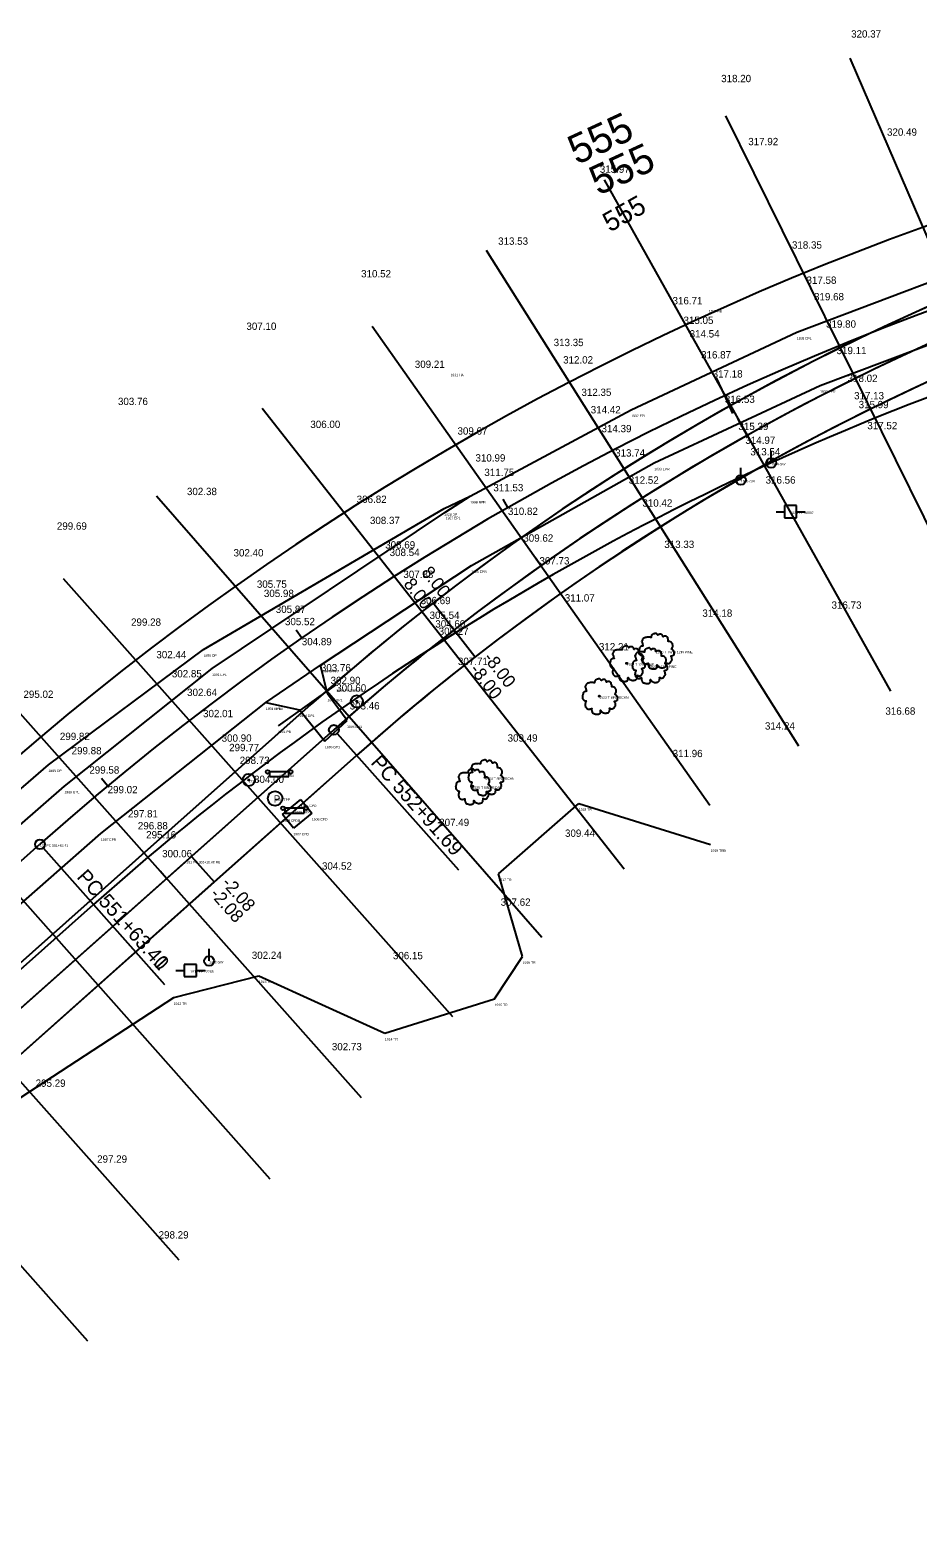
# Model space of a CAD drawing. Extents: x 49683 to 58852, y 49525 to 54803.
# Drawn here: x 56026 to 56390, y 53498 to 54115 of the extents above; entities that cross this region are included whole.
import ezdxf

# ---------------------------------------------------------------- set-up
doc = ezdxf.new("R2010")
doc.units = 0
for name, color, linetype in [('Level 1', 7, 'Continuous'), ('Level 11', 7, 'Continuous'), ('Level 12', 7, 'Continuous'), ('Level 13', 7, 'Continuous'), ('Level 19', 7, 'Continuous'), ('Level 20', 7, 'Continuous'), ('Level 21', 7, 'Continuous'), ('Level 29', 7, 'Continuous'), ('Level 3', 7, 'Continuous'), ('Level 32', 7, 'Continuous'), ('Level 50', 7, 'Continuous'), ('Level 51', 7, 'Continuous'), ('Level 53', 7, 'Continuous'), ('Level 56', 7, 'Continuous'), ('Level 58', 7, 'Continuous'), ('Level 59', 7, 'Continuous'), ('Level 6', 7, 'Continuous'), ('Level 61', 7, 'Continuous'), ('Level 62', 7, 'Continuous'), ('Level 63', 7, 'Continuous'), ('Level 8', 7, 'Continuous'), ('Level 9', 7, 'Continuous')]:
    doc.layers.add(name, color=color, linetype=linetype)

# ---------------------------------------------------------------- blocks, each defined once
blk = doc.blocks.new('IP')
at = {"layer": 'Level 12'}
for radius in [2.5, 0.25]:
    blk.add_circle((0, 0), radius, dxfattribs=at)
blk = doc.blocks.new('TBX')
at = {"layer": 'Level 9'}
for p, q in [((3.99, 1.14), (-4.01, 1.14)), ((-4.01, 1.14), (-4.01, -0.82)), ((3.99, -0.82), (3.99, 1.14)), ((-4.01, -0.82), (3.99, -0.82))]:
    blk.add_line(p, q, dxfattribs=at)
for centre in [(-4.76, 1.14), (4.74, 1.14)]:
    blk.add_circle(centre, 0.75, dxfattribs=at)
blk = doc.blocks.new('TPP')
at = {"layer": 'Level 9'}
blk.add_circle((0, 0), 3, dxfattribs=at)
blk.add_text('P', height=3, dxfattribs=at).set_placement((-0.59, -1.73))
blk = doc.blocks.new('GW')
at = {"layer": 'Level 9'}
blk.add_line((0, 0), (0, 5), dxfattribs=at)
blk.add_circle((0, 0), 2, dxfattribs=at)
blk = doc.blocks.new('PP')
at = {"layer": 'Level 9'}
for p, q in [((2.53, 2.45), (-2.47, 2.45)), ((-2.47, 2.45), (-2.47, -2.55)), ((2.53, -2.55), (2.53, 2.45)), ((-5.91, -0.11), (-2.44, -0.11)), ((-2.47, -2.55), (2.53, -2.55)), ((2.45, -0.11), (6.09, -0.11))]:
    blk.add_line(p, q, dxfattribs=at)
blk = doc.blocks.new('T1')
at = {"layer": 'Level 11'}
for centre, radius in [((0, 0), 0.25), ((-0.01, -0.02), 0.0001)]:
    blk.add_circle(centre, radius, dxfattribs=at)
for points in [[(0.13, 7.17), (-0.17, 7.19), (-0.49, 7.09), (-0.74, 6.99), (-0.97, 6.92), (-1.19, 6.82), (-1.49, 6.64), (-1.72, 6.44), (-1.84, 6.19), (-1.89, 5.97), (-1.94, 5.69), (-1.94, 5.52), (-2.07, 5.49), (-2.22, 5.52), (-2.47, 5.59), (-2.72, 5.59), (-2.97, 5.59), (-3.32, 5.57), (-3.67, 5.57), (-3.94, 5.52), (-4.27, 5.47), (-4.64, 5.34), (-4.99, 5.22), (-5.29, 4.97), (-5.54, 4.49), (-5.67, 4.14), (-5.82, 3.89), (-5.67, 3.44), (-5.49, 3.09), (-5.47, 2.89), (-5.39, 2.47), (-5.29, 2.24), (-5.17, 2.04), (-5.24, 2.02), (-5.62, 1.97), (-5.92, 1.87), (-6.34, 1.64), (-6.57, 1.42), (-6.67, 1.09), (-6.69, 0.75), (-6.79, 0.55), (-6.87, 0.27), (-6.89, 0.2), (-6.94, -0.13), (-6.84, -0.58), (-6.82, -0.93), (-6.69, -1.15), (-6.54, -1.33), (-6.37, -1.58), (-5.97, -1.8), (-5.64, -1.9), (-5.44, -1.93), (-5.62, -2.43), (-5.67, -2.78), (-5.79, -3.18), (-5.79, -3.25), (-5.84, -3.73), (-5.69, -4.05), (-5.62, -4.43), (-5.44, -4.65), (-5.17, -4.95), (-4.84, -5.18), (-4.34, -5.3), (-3.94, -5.28), (-3.37, -5.1), (-3.12, -5.03), (-3.14, -5.2), (-3.12, -5.58), (-3.12, -6), (-2.97, -6.33), (-2.87, -6.6), (-2.72, -6.85), (-2.39, -7.08), (-1.99, -7.15), (-1.57, -7.3), (-1.12, -7.38), (-0.62, -7.4), (-0.02, -7.25), (0.26, -7.13), (0.36, -6.95), (0.56, -6.58), (0.51, -6.35), (0.53, -5.75), (0.63, -5.93), (0.81, -6.28), (1.31, -6.58), (1.71, -6.75), (2.18, -6.9), (2.48, -6.98), (2.96, -6.9), (3.33, -6.83), (3.71, -6.7), (4.01, -6.43), (4.18, -6.15), (4.23, -5.88), (4.31, -5.5), (4.36, -5.33)], [(4.36, -5.33), (4.28, -5.15), (4.23, -4.9), (4.31, -4.93), (4.48, -4.98), (4.75, -5.1), (4.98, -5.18), (5.3, -5.15), (5.58, -5.05), (6.03, -4.78), (6.3, -4.3), (6.58, -3.9), (6.65, -3.58), (6.6, -3.35), (6.58, -2.85), (6.38, -2.6), (6.33, -2.48), (6.23, -2.08), (6.3, -2.03), (6.58, -1.98), (6.95, -1.85), (7.23, -1.73), (7.45, -1.55), (7.53, -1.33), (7.5, -0.93), (7.55, -0.53), (7.48, -0.38), (7.38, -0.23), (7.3, -0.03), (7.15, 0.12), (7.05, 0.27), (6.95, 0.37), (6.83, 0.52), (6.65, 0.65), (6.5, 0.7), (6.45, 0.85), (6.6, 1.04), (6.65, 1.14), (6.68, 1.37), (6.9, 1.72), (6.95, 2.12), (6.9, 2.54), (6.85, 2.82), (6.7, 3.09), (6.5, 3.34), (6.38, 3.52), (6.2, 3.64), (5.88, 3.77), (5.63, 3.82), (5.28, 3.82), (5.08, 3.87), (5.1, 3.92), (5.1, 4.07), (5.1, 4.34), (5.03, 4.79), (4.88, 5.29), (4.88, 5.32), (4.78, 5.57), (4.56, 5.77), (4.38, 5.87), (4.18, 5.99), (3.93, 6.02), (3.63, 6.02), (3.36, 5.97), (3.16, 5.87), (2.98, 5.74), (2.91, 5.89), (2.81, 6.19), (2.76, 6.34), (2.61, 6.52), (2.38, 6.72), (1.93, 6.84), (1.31, 6.77), (1.01, 6.57), (0.86, 6.39), (0.81, 6.52), (0.61, 6.72), (0.51, 6.89), (0.33, 7.02), (0.18, 7.12), (0.08, 7.17)]]:
    blk.add_spline(points, degree=3, dxfattribs=at)

msp = doc.modelspace()

# ---------------------------------------------------------------- linework, layer by layer
at = {"layer": 'Level 1'}
for p, q in [((56311, 53965.34), (56307.64, 53972.6)), ((56314.36, 53958.08), (56311, 53965.34)), ((56222.17, 53919.48), (56220.18, 53922.95)), ((56137.67, 53866.06), (56135.39, 53869.34)), ((56058.16, 53805.47), (56055.59, 53808.55)), ((55534.58, 53340.86), (56030.42, 53781.6)), ((56031.75, 53780.11), (56080.5, 53725.26))]:
    msp.add_line(p, q, dxfattribs=at)
msp.add_circle((56030.42, 53781.6), 2, dxfattribs=at)
at = {"layer": 'Level 11'}
for p, q in [((56218.32, 53769.53), (56251.21, 53798.33)), ((56251.21, 53798.33), (56305.22, 53781.48)), ((56228.2, 53735.68), (56218.32, 53769.53)), ((56216.72, 53718.3), (56228.2, 53735.68)), ((56085.22, 53718.79), (56120.13, 53727.76)), ((56120.13, 53727.76), (56171.75, 53704.22)), ((55996.99, 53661.35), (56085.22, 53718.79)), ((56171.75, 53704.22), (56216.72, 53718.3))]:
    msp.add_line(p, q, dxfattribs=at)
at = {"layer": 'Level 13'}
msp.add_line((55556.51, 53316.2), (56052.34, 53756.94), dxfattribs=at)
for radius, start in [(1178.92, 86.60044), (1112.92, 108.44495)]:
    msp.add_arc((56791.72, 52925.13), radius, start, 131.63335, dxfattribs=at)
at = {"layer": 'Level 19'}
for p, q in [((56320.22, 53949.03), (56316.31, 53956.01)), ((56320.22, 53949.03), (56324.13, 53942.05)), ((56235.67, 53895.71), (56233.36, 53898.98)), ((56157.09, 53833.94), (56154.45, 53836.95)), ((54181.77, 52078.16), (56150.85, 53828.45)), ((56152.18, 53826.95), (56201.86, 53771.06)), ((56082.32, 53767.53), (56079.66, 53770.52))]:
    msp.add_line(p, q, dxfattribs=at)
msp.add_circle((56150.85, 53828.45), 2, dxfattribs=at)
msp.add_arc((56791.96, 53107.19), 965, 83.49443, 131.63337, dxfattribs=at)
at = {"layer": 'Level 20'}
for p, q in [((54172.47, 52088.62), (56141.55, 53838.91)), ((54191.07, 52067.7), (56160.15, 53817.98))]:
    msp.add_line(p, q, dxfattribs=at)
for radius, start in [(979, 83.49447), (951, 83.49446)]:
    msp.add_arc((56791.96, 53107.19), radius, start, 131.63337, dxfattribs=at)
at = {"layer": 'Level 29'}
for p, q in [((56311, 53965.34), (56307.65, 53972.6)), ((56222.17, 53919.48), (56220.18, 53922.95)), ((56137.67, 53866.06), (56135.39, 53869.34)), ((56058.16, 53805.47), (56055.6, 53808.55)), ((55534.58, 53340.86), (56030.42, 53781.6)), ((56031.75, 53780.11), (56081.44, 53724.2))]:
    msp.add_line(p, q, dxfattribs=at)
msp.add_circle((56030.42, 53781.6), 2, dxfattribs=at)
msp.add_arc((56791.72, 52925.13), 1145.92, 83.49443, 131.63333, dxfattribs=at)
at = {"layer": 'Level 3'}
for p, q in [((56340.54, 53991.29), (56414.45, 54019.29)), ((56350.09, 53969.49), (56420.81, 53996.17)), ((56272.68, 53959.54), (56340.54, 53991.29)), ((56282.12, 53937.76), (56350.09, 53969.49)), ((56206.74, 53924.16), (56272.68, 53959.54)), ((56207.19, 53895.72), (56282.12, 53937.76)), ((56196.7, 53917.72), (56206.74, 53924.16)), ((56100.96, 53853.53), (56196.7, 53917.72)), ((56145.4, 53854.95), (56207.19, 53895.72)), ((56040.5, 53805.43), (56100.96, 53853.53)), ((56122.95, 53839.6), (56145.4, 53854.95)), ((56055.41, 53785.96), (56122.95, 53839.6)), ((55974.42, 53747.84), (56040.5, 53805.43)), ((55989.61, 53728.42), (56055.41, 53785.96))]:
    msp.add_line(p, q, dxfattribs=at)
at = {"layer": 'Level 50'}
for p, q in [((56362.31, 54103.5), (56457.35, 53883.12)), ((56311.29, 54079.91), (56417.61, 53864.75)), ((56261.55, 54053.71), (56378.88, 53844.34)), ((56213.25, 54024.97), (56341.26, 53821.96)), ((56166.49, 53993.77), (56304.84, 53797.66)), ((56121.41, 53960.18), (56269.74, 53771.5)), ((56078.14, 53924.31), (56236.03, 53743.57)), ((56039.97, 53890.44), (56199.41, 53711.06)), ((56002.6, 53857.22), (56162.04, 53677.84)), ((55965.23, 53824), (56124.67, 53644.62)), ((55927.86, 53790.78), (56087.3, 53611.4)), ((55890.49, 53757.56), (56049.93, 53578.19))]:
    msp.add_line(p, q, dxfattribs=at)
at = {"layer": 'Level 6'}
msp.add_line((56151.85, 53847.05), (56127.97, 53830.15), dxfattribs=at)
at = {"layer": 'Level 63'}
for p, q in [((56200.06, 53869.35), (56191.47, 53880.4)), ((56200.06, 53869.35), (56191.47, 53880.4)), ((56208.65, 53858.29), (56200.06, 53869.35)), ((56208.65, 53858.29), (56200.06, 53869.35)), ((56141.55, 53838.91), (56008.51, 53720.65)), ((56017.81, 53710.19), (56150.85, 53828.45)), ((56150.85, 53828.45), (56092.55, 53776.62)), ((56101.85, 53766.16), (56160.15, 53817.98)), ((54181.77, 52078.16), (56092.55, 53776.62)), ((56092.55, 53776.62), (56101.85, 53766.16)), ((56092.55, 53776.62), (56101.85, 53766.16)), ((56101.85, 53766.16), (54191.07, 52067.7))]:
    msp.add_line(p, q, dxfattribs=at)
for radius, start, end in [(979, 87.29416, 127.83345), (965, 87.29416, 127.83345), (965, 87.29416, 127.83345), (951, 87.29416, 127.83345), (979, 127.83345, 131.63336), (965, 127.83345, 131.63336), (965, 127.83345, 131.63336), (951, 127.83345, 131.63336)]:
    msp.add_arc((56791.96, 53107.19), radius, start, end, dxfattribs=at)
at = {"layer": 'Level 8'}
for p, q in [((56196.03, 53919.16), (56206.74, 53924.16)), ((56097.49, 53861.41), (56196.03, 53919.16)), ((56033.94, 53814.18), (56097.49, 53861.41)), ((56148.21, 53843.14), (56145.4, 53854.95)), ((56122.95, 53839.6), (56136.75, 53836.71)), ((56156.24, 53832.22), (56148.21, 53843.14)), ((56136.75, 53836.71), (56147.2, 53823.85)), ((56147.2, 53823.85), (56156.24, 53832.22)), ((55965.73, 53755.18), (56033.94, 53814.18)), ((56129.74, 53793.77), (56137.33, 53799.87)), ((56137.33, 53799.87), (56141.86, 53794.31)), ((56134.27, 53788.21), (56129.74, 53793.77)), ((56141.86, 53794.31), (56134.27, 53788.21))]:
    msp.add_line(p, q, dxfattribs=at)

# ---------------------------------------------------------------- block references
at = {"layer": 'Level 11'}
for p in [(56282.78, 53860.79), (56270.85, 53855.68), (56280.04, 53854.81), (56259.6, 53842.22), (56212.86, 53809.01), (56207.69, 53805.29)]:
    msp.add_blockref('T1', p, dxfattribs=at)
at = {"layer": 'Level 12'}
for p in [(56160.27, 53840.1), (56115.99, 53807.93)]:
    msp.add_blockref('IP', p, dxfattribs=at)
at = {"layer": 'Level 9'}
for name, p in [('GW', (56330.04, 53937.74)), ('GW', (56317.61, 53930.78)), ('PP', (56337.92, 53917.82)), ('TBX', (56128.43, 53810.1)), ('TPP', (56126.79, 53800.35)), ('TBX', (56134.73, 53795.2)), ('GW', (56099.74, 53733.81)), ('PP', (56092.03, 53729.94))]:
    msp.add_blockref(name, p, dxfattribs=at)

# ---------------------------------------------------------------- texts
at = {"layer": 'Level 1'}
msp.add_text('PC 551+63.41', height=6, rotation=311.63333, dxfattribs=at).set_placement((56045.2, 53767.98))
at = {"layer": 'Level 19'}
for s, height, rotation, p in [('555', 8, 29.26521, (56263.92, 54032.11)), ('PC 552+91.69', 6, 311.63336, (56165.63, 53814.83))]:
    msp.add_text(s, height=height, rotation=rotation, dxfattribs=at).set_placement(p)
at = {"layer": 'Level 21'}
for rotation, p in [(24.80363, (56250.36, 54059.71)), (24.80353, (56259.16, 54047.14))]:
    msp.add_text('555', height=12, rotation=rotation, dxfattribs=at).set_placement(p)
at = {"layer": 'Level 29'}
msp.add_text('PC 551+63.40', height=6, rotation=311.63333, dxfattribs=at).set_placement((56045.2, 53767.98))
at = {"layer": 'Level 32'}
for s, p in [('320.37', (56362.78, 54111.98)), ('318.20', (56309.54, 54093.71)), ('320.49', (56377.49, 54071.78)), ('317.92', (56320.64, 54067.9)), ('315.97', (56259.81, 54056.6)), ('313.53', (56218.15, 54027.12)), ('318.35', (56338.54, 54025.54)), ('310.52', (56162.01, 54013.76)), ('317.58', (56344.5, 54011.12)), ('319.68', (56347.59, 54004.36)), ('316.71', (56289.61, 54002.73)), ('307.10', (56115.02, 53992.26)), ('315.05', (56294.1, 53994.7)), ('319.80', (56352.52, 53993.16)), ('313.35', (56240.9, 53985.61)), ('314.54', (56296.62, 53989.15)), ('312.02', (56244.78, 53978.49)), ('316.87', (56301.31, 53980.55)), ('319.11', (56356.83, 53982.32)), ('309.21', (56184.01, 53976.69)), ('317.18', (56306.05, 53972.74)), ('318.02', (56361.35, 53970.93)), ('303.76', (56062.38, 53961.47)), ('312.35', (56252.29, 53965.21)), ('316.53', (56311.05, 53962.35)), ('317.13', (56364, 53963.82)), ('315.99', (56365.87, 53960.19)), ('314.42', (56256.1, 53958.05)), ('306.00', (56141.21, 53952.08)), ('309.67', (56201.5, 53949.37)), ('314.39', (56260.51, 53950.34)), ('315.39', (56316.61, 53951.24)), ('317.52', (56369.43, 53951.56)), ('314.97', (56319.45, 53945.57)), ('310.99', (56208.86, 53938.34)), ('313.74', (56266.09, 53940.38)), ('313.54', (56321.5, 53940.85)), ('311.75', (56212.51, 53932.41)), ('312.52', (56271.69, 53929.25)), ('316.56', (56327.75, 53929.31)), ('302.38', (56090.65, 53924.59)), ('311.53', (56216.21, 53926.14)), ('306.82', (56160.21, 53921.39)), ('310.42', (56277.27, 53919.87)), ('299.69', (56037.36, 53910.43)), ('308.37', (56165.63, 53912.73)), ('310.82', (56222.17, 53916.48)), ('309.62', (56228.48, 53905.51)), ('302.40', (56109.74, 53899.47)), ('308.69', (56171.89, 53902.72)), ('308.54', (56173.7, 53899.62)), ('313.33', (56286.24, 53902.93)), ('307.73', (56235.09, 53896.19)), ('305.75', (56119.3, 53886.64)), ('307.83', (56179.32, 53890.65)), ('305.98', (56122.18, 53882.84)), ('306.69', (56186.41, 53879.93)), ('311.07', (56245.46, 53881)), ('305.87', (56127.05, 53876.34)), ('305.54', (56190.06, 53873.89)), ('314.18', (56301.83, 53874.75)), ('316.73', (56354.77, 53878.06)), ('299.28', (56067.75, 53871.08)), ('305.52', (56130.81, 53871.31)), ('304.60', (56192.41, 53870.35)), ('305.27', (56193.79, 53867.33)), ('304.89', (56137.71, 53863.1)), ('312.21', (56259.45, 53860.99)), ('302.44', (56078.12, 53857.77)), ('307.71', (56201.69, 53855)), ('302.85', (56084.47, 53849.95)), ('303.76', (56145.53, 53852.39)), ('302.90', (56149.51, 53847.19)), ('300.60', (56151.83, 53844.12)), ('295.02', (56023.66, 53841.54)), ('302.64', (56090.72, 53842.31)), ('303.46', (56157.32, 53836.8)), ('302.01', (56097.25, 53833.63)), ('316.68', (56376.83, 53834.65)), ('299.82', (56038.59, 53824.28)), ('314.24', (56327.48, 53828.56)), ('299.88', (56043.39, 53818.43)), ('300.90', (56104.87, 53823.58)), ('299.77', (56107.95, 53819.72)), ('309.49', (56222.04, 53823.63)), ('298.73', (56112.27, 53814.46)), ('311.96', (56289.67, 53817.27)), ('299.58', (56050.66, 53810.52)), ('304.00', (56118.14, 53806.71)), ('299.02', (56058.15, 53802.47)), ('297.81', (56066.5, 53792.58)), ('296.88', (56070.54, 53787.69)), ('307.49', (56194.01, 53789.04)), ('295.16', (56073.94, 53783.98)), ('309.44', (56245.55, 53784.64)), ('300.06', (56080.48, 53776.26)), ('304.52', (56145.98, 53771.2)), ('307.62', (56219.18, 53756.4)), ('302.24', (56117.22, 53734.64)), ('306.15', (56175.04, 53734.51)), ('302.73', (56150.02, 53697.21)), ('295.29', (56028.66, 53682.26)), ('297.29', (56053.85, 53651.19)), ('298.29', (56079.05, 53620.12))]:
    msp.add_text(s, height=3, dxfattribs=at).set_placement(p)
at = {"layer": 'Level 51'}
for s, p in [('173 PC 551+63.41 ', (56030.42, 53780.6)), ('181 PC 552+10.88 RE ', (56090.45, 53773.76))]:
    msp.add_text(s, height=1, dxfattribs=at).set_placement(p)
at = {"layer": 'Level 53'}
for s, p in [('1938 EPL ', (56340.54, 53988.29)), ('1937 EPR ', (56350.09, 53966.49)), ('1932 EPL ', (56272.68, 53956.54)), ('1933 EPR ', (56282.12, 53934.76)), ('1930 EPL ', (56206.74, 53921.16)), ('1927 EPL ', (56196.7, 53914.72)), ('1926 EPR ', (56207.19, 53892.72)), ('1899 EPR ', (56145.4, 53851.95)), ('1891 EPL ', (56100.96, 53850.53)), ('1892 EPR ', (56122.95, 53836.6)), ('1888 EPL ', (56040.5, 53802.43)), ('1887 EPR ', (56055.41, 53782.96))]:
    msp.add_text(s, height=1, dxfattribs=at).set_placement(p)
at = {"layer": 'Level 56'}
for s, p in [('1900 PA 18IN RC ', (56151.85, 53844.05)), ('1901 PB ', (56127.97, 53827.15))]:
    msp.add_text(s, height=1, dxfattribs=at).set_placement(p)
at = {"layer": 'Level 58'}
for s, p in [('1929 DPB ', (56206.74, 53921.16)), ('1928 DP ', (56196.03, 53916.16)), ('1890 DP ', (56097.49, 53858.41)), ('1898 DP1B ', (56145.4, 53851.95)), ('1897 DP1 ', (56148.21, 53840.14)), ('1893 DP1A ', (56122.95, 53836.6)), ('1894 DP1 ', (56136.75, 53833.71)), ('1896 DP1 ', (56156.24, 53829.22)), ('1895 DP1 ', (56147.2, 53820.85)), ('1889 DP ', (56033.94, 53811.18)), ('1905 CPD ', (56137.33, 53796.87)), ('1904 CPDA ', (56129.74, 53790.77)), ('1908 CPDB ', (56129.74, 53790.77)), ('1906 CPD ', (56141.86, 53791.31)), ('1907 CPD ', (56134.27, 53785.21))]:
    msp.add_text(s, height=1, dxfattribs=at).set_placement(p)
at = {"layer": 'Level 59'}
for s, p in [('1934 GW ', (56330.04, 53936.74)), ('1935 GW ', (56317.61, 53929.78)), ('1936 PP 08897 ', (56337.92, 53916.82)), ('1902 TBX ', (56128.43, 53809.1)), ('1903 TPP ', (56126.79, 53799.35)), ('1909 TBX ', (56134.73, 53794.2)), ('1911 PP 72288 ', (56092.03, 53728.94)), ('1910 GW ', (56099.74, 53732.81))]:
    msp.add_text(s, height=1, dxfattribs=at).set_placement(p)
at = {"layer": 'Level 61'}
for s, p in [('1939 HB ', (56304.49, 53999.43)), ('1931 HA ', (56198.67, 53973.27)), ('1920 T TWIN 12IN PINE ', (56282.78, 53859.79)), ('1922 T 12IN PINE ', (56270.85, 53854.68)), ('1921 T 12IN PINE ', (56280.04, 53853.81)), ('1923 T 8IN PECAN ', (56259.6, 53841.22)), ('1924 T 8IN PECAN ', (56212.86, 53808.01)), ('1925 T 8IN PECAN ', (56207.69, 53804.29)), ('1918 TR ', (56251.21, 53795.33)), ('1919 TRB ', (56305.22, 53778.48)), ('1917 TR ', (56218.32, 53766.53)), ('1916 TR ', (56228.2, 53732.68)), ('1913 TR ', (56120.13, 53724.76)), ('1912 TR ', (56085.22, 53715.79)), ('1915 TR ', (56216.72, 53715.3)), ('1914 TR ', (56171.75, 53701.22))]:
    msp.add_text(s, height=1, dxfattribs=at).set_placement(p)
at = {"layer": 'Level 62'}
for s, p in [('1715 IP ', (56160.27, 53839.1)), ('1716 IP ', (56115.99, 53806.93))]:
    msp.add_text(s, height=1, dxfattribs=at).set_placement(p)
at = {"layer": 'Level 63'}
for s, rotation, p in [('8.00', 307.83368, (56186.48, 53892.92)), ('8.00', 307.83368, (56179.17, 53888.11)), ('-8.00', 307.83347, (56211.85, 53857.84)), ('-8.00', 307.83347, (56206.27, 53853.06)), ('-2.08', 311.63346, (56104.59, 53765.49)), ('-2.08', 311.63346, (56099.82, 53760.98))]:
    msp.add_text(s, height=5.25, rotation=rotation, dxfattribs=at).set_placement(p)

doc.saveas('drawing.dxf')
